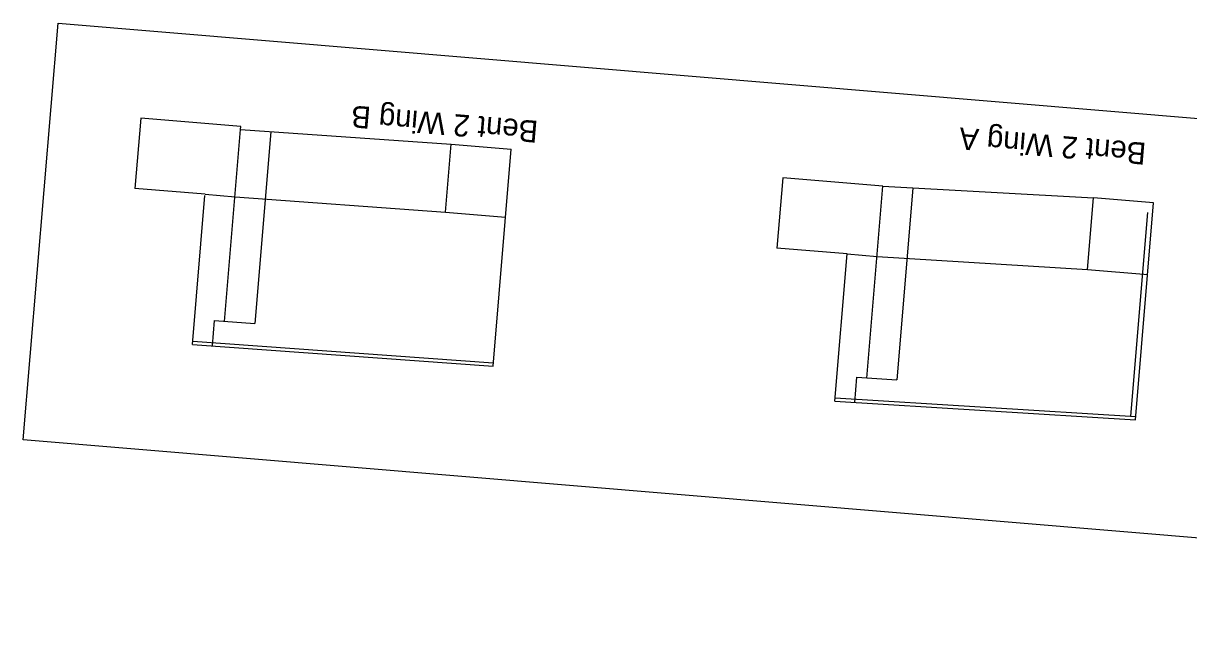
# Model space of a CAD drawing. Extents: x 1313815 to 1314857, y 2089008 to 2089414.
# Drawn here: x 1313815.4 to 1313873.4, y 2089110.6 to 2089141.3 of the extents above; entities that cross this region are included whole.
import ezdxf

# ---------------------------------------------------------------- set-up
doc = ezdxf.new("R2010")
doc.units = 0
for name, color, linetype in [('B-Gen-Construction Line', 7, 'Continuous'), ('B-Gen-Hidden', 7, 'Continuous'), ('B-Gen-Rebar', 7, 'Continuous'), ('B-Gen-Viewport', 7, 'Continuous'), ('B-Sub-Abutment Cap (Hidden)', 7, 'Continuous'), ('B-Sub-Wingwall', 7, 'Continuous')]:
    doc.layers.add(name, color=color, linetype=linetype)

msp = doc.modelspace()

# ---------------------------------------------------------------- linework, layer by layer
at = {"layer": 'B-Gen-Construction Line'}
for p, q in [((1313823.864, 2089125.536), (1313838.825, 2089124.448)), ((1313855.838, 2089122.717), (1313870.811, 2089121.778))]:
    msp.add_line(p, q, dxfattribs=at)
at = {"layer": 'B-Gen-Hidden'}
for p, q in [((1313827.743, 2089135.948), (1313826.947, 2089126.408)), ((1313859.719, 2089133.146), (1313858.922, 2089123.608)), ((1313824.847, 2089125.297), (1313824.952, 2089126.554)), ((1313824.952, 2089126.554), (1313826.947, 2089126.408)), ((1313823.85, 2089125.37), (1313838.811, 2089124.282)), ((1313856.822, 2089122.487), (1313856.926, 2089123.734)), ((1313856.926, 2089123.734), (1313858.922, 2089123.608)), ((1313855.824, 2089122.551), (1313870.798, 2089121.612))]:
    msp.add_line(p, q, dxfattribs=at)
at = {"layer": 'B-Gen-Rebar'}
msp.add_line((1313870.562, 2089121.793), (1313871.408, 2089131.935), dxfattribs=at)
at = {"layer": 'B-Gen-Viewport'}
msp.add_lwpolyline([(1313935.133, 2089110.63), (1313815.428, 2089120.622), (1313817.158, 2089141.347), (1313936.863, 2089131.354)], close=True, dxfattribs=at)
at = {"layer": 'B-Sub-Abutment Cap (Hidden)'}
for p, q in [((1313825.451, 2089126.516), (1313826.247, 2089136.057)), ((1313836.441, 2089131.957), (1313836.723, 2089135.327)), ((1313857.425, 2089123.696), (1313858.221, 2089133.238)), ((1313824.474, 2089132.844), (1313825.968, 2089132.719)), ((1313825.968, 2089132.719), (1313836.441, 2089131.957)), ((1313868.413, 2089129.104), (1313868.709, 2089132.657)), ((1313836.441, 2089131.957), (1313839.431, 2089131.708)), ((1313856.435, 2089129.875), (1313857.93, 2089129.75)), ((1313857.93, 2089129.75), (1313868.413, 2089129.104)), ((1313868.413, 2089129.104), (1313871.402, 2089128.855))]:
    msp.add_line(p, q, dxfattribs=at)
at = {"layer": 'B-Sub-Wingwall'}
for p, q in [((1313821.277, 2089136.623), (1313820.986, 2089133.135)), ((1313826.26, 2089136.207), (1313821.277, 2089136.623)), ((1313826.247, 2089136.057), (1313826.26, 2089136.207)), ((1313826.247, 2089136.057), (1313836.723, 2089135.327)), ((1313836.723, 2089135.327), (1313839.712, 2089135.077)), ((1313838.811, 2089124.282), (1313839.712, 2089135.077)), ((1313853.238, 2089133.654), (1313852.947, 2089130.166)), ((1313858.221, 2089133.238), (1313853.238, 2089133.654)), ((1313824.474, 2089132.844), (1313820.986, 2089133.135)), ((1313858.221, 2089133.238), (1313868.709, 2089132.657)), ((1313823.85, 2089125.37), (1313824.468, 2089132.772)), ((1313871.699, 2089132.407), (1313868.709, 2089132.657)), ((1313870.798, 2089121.612), (1313871.699, 2089132.407)), ((1313856.435, 2089129.875), (1313852.947, 2089130.166)), ((1313855.824, 2089122.551), (1313856.435, 2089129.875))]:
    msp.add_line(p, q, dxfattribs=at)

# ---------------------------------------------------------------- texts
at = {"layer": 'B-Sub-Abutment Cap (Hidden)'}
for s, p in [('Bent 2 Wing B', (1313841.089, 2089136.486)), ('Bent 2 Wing A', (1313871.359, 2089135.393))]:
    msp.add_text(s, height=1.09106, rotation=175.22842, dxfattribs=at).set_placement(p)

doc.saveas('drawing.dxf')
